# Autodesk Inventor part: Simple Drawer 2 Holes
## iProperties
Created: 2006-01
Part Number: Simple Drawer 2 Holes
Document SubType Name: Modeling
Designer: Martin
Material: Wood_Pine
d22: 650,000 mm
d0: 600,000 mm
d1: 500,000 mm
Width: 600,000 mm
Draw_Height: 100,000 mm
d2: 100,000 mm
Author: Martin
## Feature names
1. Extrusion1
2. Shell1
3. Extrusion2
4. Hole1
5. Rectangular Pattern1
